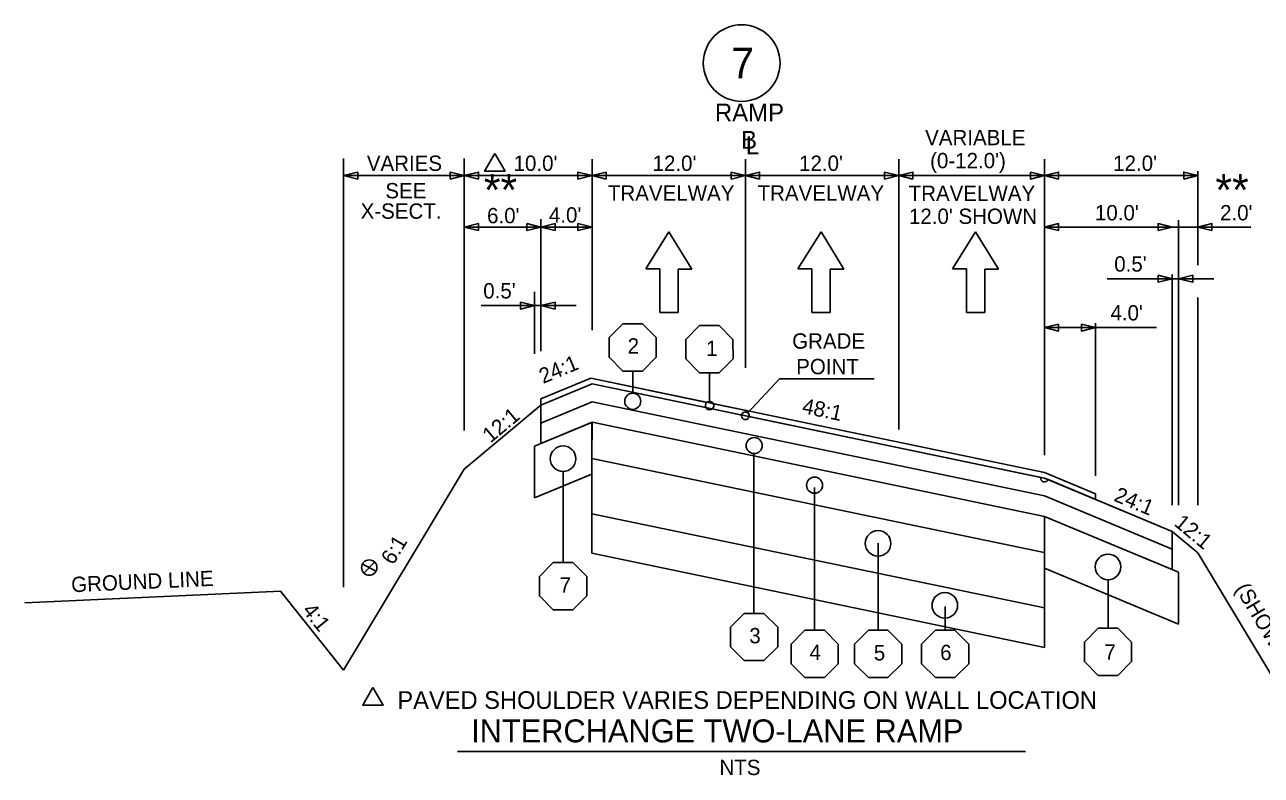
# Model space of a CAD drawing. Extents: x 4649 to 5578, y 4853 to 5383.
# Drawn here: x 5068.2 to 5164.9, y 5247.4 to 5306.2 of the extents above; entities that cross this region are included whole.
import ezdxf

# ---------------------------------------------------------------- set-up
doc = ezdxf.new("R2010")
doc.units = 0
for name, color, linetype in [('Level 25', 7, 'Continuous'), ('RD_QTY_OGFC', 7, 'Continuous'), ('RD_QTY_Stab_Agg_2', 7, 'Continuous'), ('RD_QTY_Sub_Base', 7, 'Continuous'), ('RD_SHT_Bndy', 7, 'Continuous'), ('RD_SHT_Typical', 7, 'Continuous'), ('RD_Sketch1', 7, 'Continuous'), ('RD_Sketch2', 7, 'Continuous'), ('RD_TX_TypSect', 7, 'Continuous'), ('RD_XS_Base', 7, 'Continuous'), ('RD_XS_EarthShd', 7, 'Continuous')]:
    doc.layers.add(name, color=color, linetype=linetype)

msp = doc.modelspace()

# ---------------------------------------------------------------- linework, layer by layer
at = {"layer": 'Level 25'}
for p, q in [((5127.234, 5278.453), (5124.75, 5275.798)), ((5134.63, 5278.454), (5127.234, 5278.453))]:
    msp.add_line(p, q, dxfattribs=at)
msp.add_circle((5124.265, 5303.18), 3, dxfattribs=at)
at = {"layer": 'RD_QTY_OGFC'}
for p, q in [((5112.452, 5278.517), (5108.564, 5276.897)), ((5108.564, 5276.399), (5112.562, 5278.065)), ((5121.546, 5276.623), (5112.452, 5278.517)), ((5112.562, 5278.065), (5121.462, 5276.211)), ((5108.564, 5276.897), (5108.564, 5276.399))]:
    msp.add_line(p, q, dxfattribs=at)
msp.add_arc((5121.756, 5276.366), 0.332, 129.2008, 207.76001, dxfattribs=at)
at = {"layer": 'RD_QTY_Stab_Agg_2'}
for p, q in [((5112.562, 5275.074), (5108.564, 5273.408)), ((5112.555, 5272.237), (5112.562, 5275.074)), ((5108.564, 5273.408), (5108.064, 5273.2)), ((5108.064, 5273.2), (5108.064, 5269.139)), ((5112.555, 5272.233), (5112.535, 5272.237)), ((5112.551, 5271.023), (5112.555, 5272.233)), ((5108.064, 5269.139), (5112.551, 5271.009)), ((5112.551, 5271.009), (5112.551, 5271.023)), ((5147.953, 5263.639), (5158.449, 5259.266)), ((5158.449, 5259.266), (5158.449, 5263.327))]:
    msp.add_line(p, q, dxfattribs=at)
for points in [[(5112.535, 5272.237), (5112.555, 5272.237)], [(5147.953, 5267.7), (5147.953, 5264.863), (5147.953, 5263.639)], [(5158.449, 5263.327), (5157.949, 5263.535), (5147.953, 5267.7)]]:
    msp.add_lwpolyline(points, dxfattribs=at)
at = {"layer": 'RD_QTY_Sub_Base'}
for p, q in [((5112.543, 5267.906), (5112.535, 5264.809)), ((5147.953, 5260.527), (5112.543, 5267.906)), ((5112.535, 5264.809), (5147.953, 5257.429)), ((5147.953, 5257.429), (5147.953, 5260.527))]:
    msp.add_line(p, q, dxfattribs=at)
at = {"layer": 'RD_SHT_Bndy'}
for p, q in [((5116.757, 5287.061), (5118.579, 5289.976)), ((5118.579, 5289.976), (5120.363, 5287.052)), ((5128.651, 5287.062), (5130.473, 5289.976)), ((5130.473, 5289.976), (5132.257, 5287.052)), ((5140.748, 5287.062), (5142.57, 5289.977)), ((5142.57, 5289.977), (5144.354, 5287.052)), ((5117.85, 5287.061), (5116.757, 5287.061)), ((5117.85, 5287.061), (5117.85, 5283.66)), ((5119.306, 5287.052), (5120.363, 5287.052)), ((5119.306, 5287.052), (5119.307, 5283.652)), ((5129.743, 5287.061), (5128.651, 5287.062)), ((5129.743, 5287.061), (5129.744, 5283.661)), ((5131.2, 5287.052), (5132.257, 5287.052)), ((5131.2, 5287.052), (5131.2, 5283.652)), ((5141.841, 5287.062), (5140.748, 5287.062)), ((5141.841, 5287.062), (5141.841, 5283.661)), ((5143.298, 5287.052), (5144.354, 5287.052)), ((5143.298, 5287.052), (5143.298, 5283.652)), ((5117.85, 5283.66), (5119.307, 5283.652)), ((5129.744, 5283.661), (5131.2, 5283.652)), ((5141.841, 5283.661), (5143.298, 5283.652))]:
    msp.add_line(p, q, dxfattribs=at)
at = {"layer": 'RD_SHT_Typical'}
for p, q in [((5108.564, 5276.897), (5112.452, 5278.517)), ((5108.564, 5276.399), (5112.562, 5278.065)), ((5108.564, 5276.399), (5102.566, 5271.401)), ((5108.564, 5276.399), (5108.564, 5276.897)), ((5108.564, 5275.003), (5112.562, 5276.67)), ((5108.564, 5276.399), (5108.564, 5273.408)), ((5121.963, 5276.107), (5124.265, 5275.628)), ((5124.874, 5275.93), (5122.051, 5276.518)), ((5108.064, 5273.2), (5112.585, 5275.084)), ((5112.535, 5275.094), (5112.535, 5264.809)), ((5124.75, 5275.798), (5124.874, 5275.93)), ((5124.874, 5275.93), (5124.75, 5275.797)), ((5124.852, 5275.505), (5147.659, 5270.752)), ((5147.953, 5271.12), (5124.874, 5275.93)), ((5108.064, 5273.2), (5108.064, 5269.139)), ((5102.566, 5271.401), (5093.123, 5255.661)), ((5108.064, 5269.139), (5112.585, 5271.023)), ((5147.659, 5270.752), (5147.953, 5270.691)), ((5151.952, 5269.454), (5147.953, 5271.12)), ((5151.952, 5269.454), (5147.953, 5271.12)), ((5157.949, 5266.526), (5147.953, 5270.691)), ((5157.949, 5265.13), (5147.953, 5269.295)), ((5151.952, 5269.454), (5151.952, 5269.027)), ((5151.952, 5269.027), (5151.952, 5269.454)), ((5147.953, 5267.7), (5147.953, 5257.429)), ((5158.449, 5263.327), (5147.953, 5267.7)), ((5157.949, 5266.526), (5159.949, 5264.846)), ((5157.949, 5266.512), (5157.949, 5263.535)), ((5159.949, 5264.846), (5168.327, 5250.883)), ((5158.449, 5259.266), (5147.953, 5263.639)), ((5158.449, 5263.327), (5158.449, 5259.266)), ((5088.182, 5261.838), (5093.123, 5255.661))]:
    msp.add_line(p, q, dxfattribs=at)
for points in [[(5112.452, 5278.517), (5147.953, 5271.12)], [(5112.562, 5278.065), (5147.953, 5270.691)], [(5112.562, 5276.67), (5147.953, 5269.295)], [(5112.562, 5275.074), (5147.953, 5267.7)], [(5124.75, 5275.797), (5124.75, 5275.798)], [(5112.535, 5272.237), (5147.925, 5264.863)], [(5147.953, 5270.691), (5148.23, 5270.576), (5151.952, 5269.025)], [(5151.952, 5269.025), (5151.952, 5269.027)], [(5112.535, 5267.907), (5147.953, 5260.527)], [(5112.535, 5264.809), (5147.953, 5257.429)]]:
    msp.add_lwpolyline(points, dxfattribs=at)
for centre, radius, start, end in [((5121.756, 5276.366), 0.332, 308.70707, 27.26628), ((5124.558, 5275.567), 0.3, 50.33988, 168.23354), ((5124.558, 5275.567), 0.3, 348.23354, 50.33988)]:
    msp.add_arc(centre, radius, start, end, dxfattribs=at)
at = {"layer": 'RD_Sketch1'}
msp.add_line((5068.178, 5260.926), (5088.212, 5261.839), dxfattribs=at)
at = {"layer": 'RD_Sketch2'}
for points in [[(5117.588, 5281.687), (5117.588, 5280.157), (5116.506, 5279.075), (5114.977, 5279.075), (5113.895, 5280.157), (5113.895, 5281.687), (5114.977, 5282.768), (5116.506, 5282.768)], [(5123.586, 5281.55), (5123.587, 5280.021), (5122.505, 5278.939), (5120.976, 5278.939), (5119.894, 5280.021), (5119.894, 5281.55), (5120.975, 5282.632), (5122.505, 5282.632)], [(5112.141, 5263.002), (5112.141, 5261.473), (5111.06, 5260.391), (5109.53, 5260.391), (5108.448, 5261.472), (5108.448, 5263.002), (5109.53, 5264.084), (5111.059, 5264.084)], [(5127.082, 5259.024), (5127.082, 5257.494), (5126.001, 5256.412), (5124.471, 5256.412), (5123.39, 5257.494), (5123.39, 5259.023), (5124.471, 5260.105), (5126.001, 5260.105)], [(5131.822, 5257.698), (5131.822, 5256.168), (5130.74, 5255.087), (5129.211, 5255.086), (5128.129, 5256.168), (5128.129, 5257.698), (5129.21, 5258.779), (5130.74, 5258.779)], [(5136.79, 5257.698), (5136.79, 5256.168), (5135.709, 5255.087), (5134.179, 5255.087), (5133.097, 5256.168), (5133.097, 5257.698), (5134.179, 5258.779), (5135.709, 5258.779)], [(5142.03, 5257.698), (5142.03, 5256.168), (5140.948, 5255.087), (5139.419, 5255.087), (5138.337, 5256.168), (5138.337, 5257.698), (5139.419, 5258.78), (5140.948, 5258.78)], [(5154.775, 5257.859), (5154.775, 5256.329), (5153.694, 5255.247), (5152.164, 5255.247), (5151.082, 5256.329), (5151.082, 5257.859), (5152.164, 5258.94), (5153.693, 5258.94)]]:
    msp.add_lwpolyline(points, close=True, dxfattribs=at)
at = {"layer": 'RD_TX_TypSect'}
for p, q in [((5093.123, 5262.148), (5093.122, 5295.7)), ((5102.566, 5274.417), (5102.566, 5295.7)), ((5112.562, 5295.666), (5112.562, 5285.204)), ((5124.558, 5295.666), (5124.558, 5279.321)), ((5136.552, 5295.666), (5136.553, 5274.501)), ((5147.952, 5295.667), (5147.953, 5272.501)), ((5112.562, 5282.283), (5112.562, 5294.499)), ((5159.946, 5294.717), (5159.946, 5287.352)), ((5093.122, 5294.375), (5102.566, 5294.375)), ((5102.566, 5294.375), (5112.562, 5294.375)), ((5112.562, 5294.375), (5124.558, 5294.375)), ((5124.557, 5294.375), (5136.553, 5294.376)), ((5136.552, 5294.376), (5147.952, 5294.376)), ((5147.952, 5294.376), (5159.946, 5294.376)), ((5108.564, 5280.635), (5108.563, 5290.956)), ((5158.449, 5268.573), (5158.448, 5290.874)), ((5102.566, 5290.337), (5108.563, 5290.338)), ((5108.563, 5290.338), (5112.562, 5290.338)), ((5147.953, 5290.339), (5157.947, 5290.339)), ((5157.947, 5290.339), (5159.946, 5290.339)), ((5159.946, 5290.339), (5164.086, 5290.339)), ((5152.857, 5286.298), (5157.947, 5286.298)), ((5157.949, 5268.573), (5157.949, 5286.638)), ((5161.212, 5286.298), (5157.95, 5286.298)), ((5108.064, 5280.409), (5108.064, 5285.279)), ((5159.948, 5284.837), (5159.948, 5268.573)), ((5103.884, 5284.2), (5108.064, 5284.2)), ((5111.329, 5284.2), (5108.064, 5284.2)), ((5151.951, 5282.814), (5151.952, 5270.864)), ((5147.953, 5282.473), (5156.713, 5282.473)), ((5153.949, 5282.473), (5153.452, 5282.473)), ((5115.742, 5279.075), (5115.742, 5277.34)), ((5121.74, 5276.697), (5121.74, 5278.939)), ((5125.229, 5260.105), (5125.229, 5272.61)), ((5110.295, 5264.084), (5110.294, 5271.21)), ((5129.968, 5258.779), (5129.968, 5269.958)), ((5134.937, 5258.779), (5134.936, 5265.604)), ((5094.591, 5263.955), (5095.664, 5263.407)), ((5094.714, 5263.262), (5095.541, 5264.106)), ((5152.929, 5258.94), (5152.928, 5262.744)), ((5140.176, 5258.78), (5140.176, 5260.632)), ((5102.024, 5249.3), (5146.478, 5249.301))]:
    msp.add_line(p, q, dxfattribs=at)
for points in [[(5104.956, 5296.11), (5104.156, 5294.725), (5105.755, 5294.725)], [(5094.225, 5294.1), (5094.225, 5294.649), (5093.122, 5294.375)], [(5101.463, 5294.1), (5101.463, 5294.65), (5102.566, 5294.375)], [(5103.668, 5294.1), (5103.668, 5294.65), (5102.566, 5294.375)], [(5111.459, 5294.1), (5111.459, 5294.65), (5112.562, 5294.375)], [(5113.664, 5294.65), (5113.664, 5294.1), (5112.562, 5294.375)], [(5123.454, 5294.65), (5123.454, 5294.101), (5124.557, 5294.375)], [(5125.661, 5294.101), (5125.661, 5294.65), (5124.559, 5294.375)], [(5135.45, 5294.651), (5135.45, 5294.101), (5136.552, 5294.376)], [(5137.656, 5294.101), (5137.656, 5294.651), (5136.554, 5294.376)], [(5146.848, 5294.651), (5146.848, 5294.101), (5147.951, 5294.376)], [(5149.055, 5294.101), (5149.055, 5294.651), (5147.952, 5294.376)], [(5158.844, 5294.102), (5158.844, 5294.651), (5159.946, 5294.376)], [(5103.668, 5290.063), (5103.668, 5290.612), (5102.566, 5290.337)], [(5107.461, 5290.612), (5107.461, 5290.063), (5108.563, 5290.338)], [(5109.666, 5290.063), (5109.666, 5290.613), (5108.563, 5290.338)], [(5111.459, 5290.613), (5111.459, 5290.063), (5112.562, 5290.338)], [(5149.055, 5290.064), (5149.055, 5290.614), (5147.953, 5290.339)], [(5156.844, 5290.064), (5156.844, 5290.614), (5157.947, 5290.339)], [(5161.049, 5290.064), (5161.049, 5290.614), (5159.946, 5290.339)], [(5156.845, 5286.573), (5156.845, 5286.023), (5157.947, 5286.298)], [(5159.549, 5286.573), (5159.55, 5286.023), (5158.447, 5286.298)], [(5106.961, 5284.475), (5106.961, 5283.925), (5108.064, 5284.2)], [(5109.666, 5284.475), (5109.666, 5283.925), (5108.564, 5284.2)], [(5149.054, 5282.749), (5149.054, 5282.199), (5147.951, 5282.474)], [(5150.849, 5282.748), (5150.849, 5282.198), (5151.951, 5282.473)], [(5095.416, 5254.299), (5094.617, 5252.915), (5096.216, 5252.915)]]:
    msp.add_lwpolyline(points, close=True, dxfattribs=at)
for centre, radius in [((5115.742, 5276.704), 0.63), ((5121.756, 5276.366), 0.332), ((5124.558, 5275.567), 0.3), ((5110.294, 5272.21), 1), ((5125.247, 5273.239), 0.63), ((5129.968, 5270.137), 0.63), ((5134.936, 5265.583), 1), ((5152.928, 5263.743), 1), ((5095.133, 5263.687), 0.6), ((5140.158, 5260.732), 1)]:
    msp.add_circle(centre, radius, dxfattribs=at)
at = {"layer": 'RD_XS_Base'}
for p, q in [((5112.562, 5278.065), (5108.564, 5276.399)), ((5147.659, 5270.752), (5112.562, 5278.065)), ((5108.564, 5275.003), (5112.562, 5276.67)), ((5108.564, 5276.399), (5108.564, 5275.003)), ((5112.562, 5276.67), (5147.953, 5269.295)), ((5157.949, 5266.512), (5148.23, 5270.575)), ((5147.953, 5269.295), (5157.949, 5265.13)), ((5157.949, 5265.13), (5157.949, 5266.512))]:
    msp.add_line(p, q, dxfattribs=at)
msp.add_circle((5115.742, 5276.704), 0.63, dxfattribs=at)
msp.add_arc((5147.953, 5270.691), 0.3, 168.23354, 337.31335, dxfattribs=at)
at = {"layer": 'RD_XS_EarthShd'}
for p, q in [((5112.562, 5276.67), (5108.564, 5275.003)), ((5147.953, 5269.295), (5112.562, 5276.67)), ((5108.564, 5273.408), (5112.562, 5275.074)), ((5112.562, 5275.074), (5147.953, 5267.7)), ((5108.564, 5275.003), (5108.564, 5273.408)), ((5157.949, 5265.13), (5147.953, 5269.295)), ((5147.953, 5267.7), (5157.949, 5263.535)), ((5157.949, 5263.535), (5157.949, 5265.13))]:
    msp.add_line(p, q, dxfattribs=at)

# ---------------------------------------------------------------- texts
at = {"layer": 'Level 25'}
for s, height, p in [('7', 2.4, (5123.443, 5301.98)), ('RAMP', 1.4, (5122.172, 5298.608)), ('B ', 1.4, (5124.219, 5296.469)), ('GRADE', 1.2, (5128.216, 5280.824)), ('POINT', 1.2, (5128.528, 5278.825))]:
    msp.add_text(s, height=height, rotation=0.00163, dxfattribs=at).set_placement(p)
at = {"layer": 'RD_TX_TypSect'}
for s, height, rotation, p in [('L', 1.4, 0.00163, (5124.584, 5296.042)), ('VARIABLE', 1.2, 0.00163, (5138.618, 5296.745)), ('VARIES', 1.2, 0.00163, (5094.94, 5294.738)), ("10.0'", 1.2, 0.00163, (5106.422, 5294.739)), ("12.0'", 1.2, 0.00163, (5117.294, 5294.739)), ("12.0'", 1.2, 0.00163, (5128.757, 5294.739)), ("(0-12.0')", 1.2, 0.00163, (5139.007, 5294.945)), ("12.0'", 1.2, 0.00163, (5153.328, 5294.74)), ('**', 2.5, 0.00163, (5104.099, 5291.999)), ('**', 2.5, 0.00163, (5161.325, 5292.001)), ('SEE', 1.2, 0.00163, (5096.39, 5292.59)), ('TRAVELWAY', 1.2, 0.00163, (5113.799, 5292.406)), ('TRAVELWAY', 1.2, 0.00163, (5125.508, 5292.407)), ('TRAVELWAY', 1.2, 0.00163, (5137.329, 5292.387)), ('X-SECT.', 1.2, 0.00163, (5094.454, 5290.993)), ("6.0'", 1.2, 0.00163, (5104.348, 5290.638)), ("4.0'", 1.2, 0.00163, (5109.185, 5290.69)), ("12.0' SHOWN", 1.2, 0.00163, (5137.351, 5290.587)), ("10.0'", 1.2, 0.00163, (5151.901, 5290.866)), ("2.0'", 1.2, 0.00163, (5161.691, 5290.866)), ("0.5'", 1.2, 0.00163, (5153.411, 5286.854)), ("0.5'", 1.2, 0.00163, (5104.047, 5284.756)), ("4.0'", 1.2, 0.00163, (5153.114, 5283.03)), ('2', 1.2, 0.00163, (5115.344, 5280.439)), ('1', 1.2, 0.00163, (5121.485, 5280.248)), ('24:1', 1.2, 22.62068, (5108.728, 5278.058)), ('12:1', 1.2, 39.8072, (5104.613, 5273.393)), ('48:1', 1.2, 348.23334, (5128.933, 5275.789)), ('24:1', 1.2, 337.38176, (5153.307, 5268.937)), ('12:1', 1.2, 320.19549, (5158.026, 5267.038)), ('6:1', 1.2, 59.03787, (5097.007, 5263.833)), ('GROUND LINE', 1.2, 2.61117, (5071.837, 5261.752)), ('7', 1.2, 0.00163, (5110.016, 5261.723)), ('(SHOWN 6:1)', 1.2, 300.96538, (5162.834, 5262.035)), ('4:1', 1.2, 308.66144, (5089.841, 5260.314)), ('3', 1.2, 0.00163, (5124.863, 5257.762)), ('4', 1.2, 0.00163, (5129.576, 5256.466)), ('6', 1.2, 0.00163, (5139.795, 5256.446)), ('7', 1.2, 0.00163, (5152.638, 5256.477)), ('5', 1.2, 0.00163, (5134.604, 5256.418)), ('PAVED SHOULDER VARIES DEPENDING ON WALL LOCATION', 1.3845, 0.00163, (5097.33, 5252.63)), ('INTERCHANGE TWO-LANE RAMP', 1.8, 0.00163, (5103.102, 5250.006)), ('NTS', 1.2, 0.00163, (5122.527, 5247.45))]:
    msp.add_text(s, height=height, rotation=rotation, dxfattribs=at).set_placement(p)

doc.saveas('drawing.dxf')
